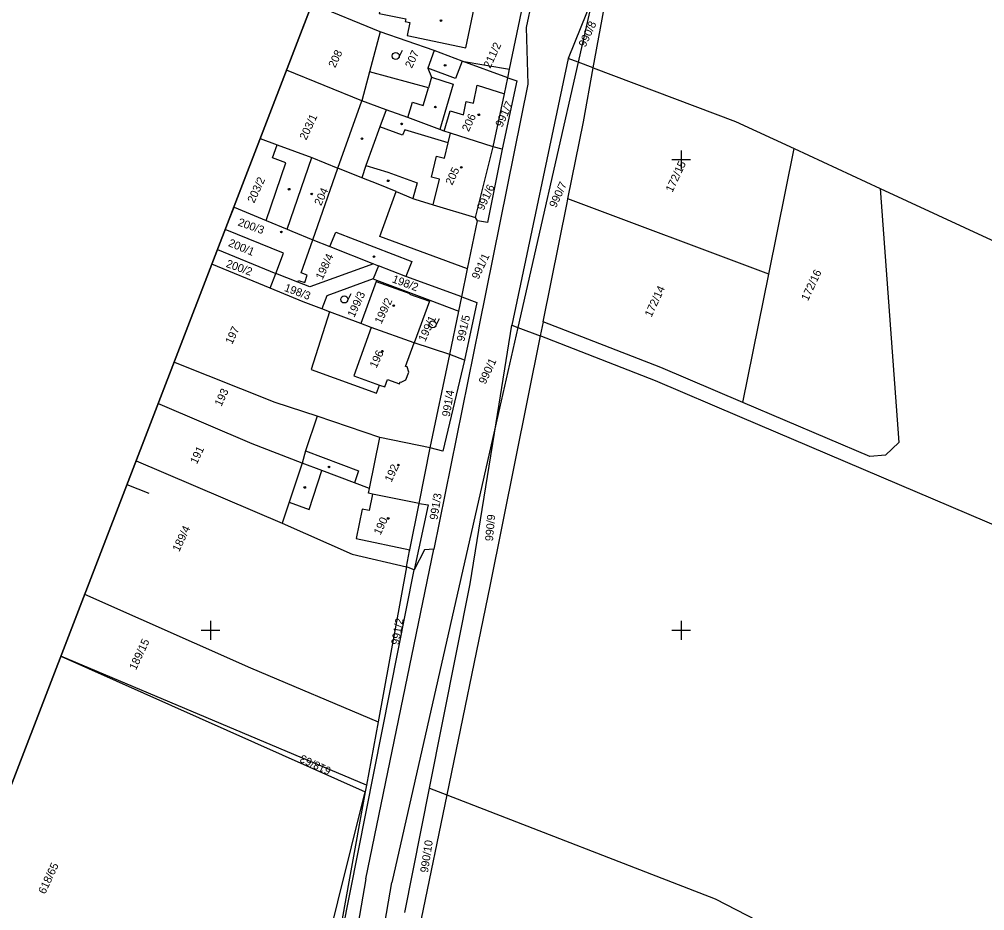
# Model space of a CAD drawing. Extents: x -755344 to -754412, y -1162670 to -1161477.
# Drawn here: x -755140.6 to -754935.5, y -1161959.6 to -1161770.1 of the extents above; entities that cross this region are included whole.
import ezdxf

# ---------------------------------------------------------------- set-up
doc = ezdxf.new("R2010")
doc.units = 0
for name, color, linetype in [('Formát', 7, 'Continuous'), ('Síť', 7, 'Continuous'), ('Vrstva 55', 7, 'Continuous'), ('Vrstva 56', 7, 'Continuous'), ('Vrstva 57', 7, 'Continuous'), ('Vrstva 58', 7, 'Continuous'), ('Vrstva 59', 7, 'Continuous')]:
    doc.layers.add(name, color=color, linetype=linetype)

msp = doc.modelspace()

# ---------------------------------------------------------------- linework, layer by layer
at = {"layer": 'Formát'}
for p, q in [((-755042.37, -1161673.02), (-755344.08, -1162456.97)), ((-755042.37, -1161673.02), (-755344.08, -1162456.97)), ((-755117.8, -1161869.01), (-755113.13, -1161870.81))]:
    msp.add_line(p, q, dxfattribs=at)
msp.add_lwpolyline([(-754488.01, -1161886.37), (-754789.71, -1162670.32), (-755344.08, -1162456.97), (-755042.37, -1161673.02)], close=True, dxfattribs=at)
msp.add_lwpolyline([(-754789.71, -1162670.32), (-754488.01, -1161886.37), (-755042.37, -1161673.02), (-755344.08, -1162456.97)], dxfattribs=at)
at = {"layer": 'Síť'}
for points in [[(-755000, -1161798), (-755000, -1161800), (-755000, -1161802)], [(-754998, -1161800), (-755000, -1161800), (-755002, -1161800)], [(-755100, -1161898), (-755100, -1161900), (-755100, -1161902)], [(-755000, -1161898), (-755000, -1161900), (-755000, -1161902)], [(-755098, -1161900), (-755100, -1161900), (-755102, -1161900)], [(-754998, -1161900), (-755000, -1161900), (-755002, -1161900)]]:
    msp.add_lwpolyline(points, dxfattribs=at)
at = {"layer": 'Vrstva 55'}
for p, q in [((-755036.5, -1161780.73), (-755029.37, -1161746.66)), ((-755018.69, -1161780.44), (-755012.38, -1161745.91)), ((-755018.66, -1161765.05), (-755023.99, -1161778.44)), ((-755063.99, -1161772.75), (-755078.47, -1161766.81)), ((-755063.99, -1161772.75), (-755066.23, -1161781.24)), ((-755052.51, -1161776.75), (-755063.99, -1161772.75)), ((-755046.56, -1161779), (-755052.51, -1161776.75)), ((-755036.87, -1161782.52), (-755046.56, -1161779)), ((-755046.56, -1161779), (-755036.5, -1161780.73)), ((-755023.99, -1161778.44), (-755035.96, -1161835.09)), ((-755067.86, -1161787.41), (-755083.88, -1161780.88)), ((-755066.23, -1161781.24), (-755067.86, -1161787.41)), ((-755036.87, -1161782.52), (-755036.5, -1161780.73)), ((-755072.94, -1161801.75), (-755067.86, -1161787.41)), ((-755038.07, -1161797.72), (-755039.95, -1161797.18)), ((-754981.41, -1161824.3), (-754976.02, -1161797.59)), ((-754976.02, -1161797.59), (-754957.73, -1161806.07)), ((-754981.41, -1161824.3), (-755024.07, -1161808.23)), ((-755095.09, -1161810.02), (-755094.97, -1161810.07)), ((-755094.97, -1161810.07), (-755088.17, -1161812.84)), ((-755045.44, -1161823.16), (-755043.26, -1161812.92)), ((-755098.56, -1161819.02), (-755086.12, -1161824.14)), ((-755087.3, -1161827.26), (-755099.76, -1161822.16)), ((-755064.35, -1161822.48), (-755065.45, -1161825.27)), ((-755065.41, -1161822.06), (-755064.35, -1161822.48)), ((-755087.3, -1161827.26), (-755086.12, -1161824.14)), ((-755081.43, -1161826), (-755086.12, -1161824.14)), ((-755046.61, -1161829.09), (-755045.44, -1161823.16)), ((-754986.91, -1161851.57), (-754981.41, -1161824.3)), ((-755065.45, -1161825.27), (-755064.74, -1161825.54)), ((-755064.74, -1161825.54), (-755053.39, -1161829.8)), ((-755053.39, -1161829.8), (-755047.24, -1161832.11)), ((-755047.24, -1161832.11), (-755046.61, -1161829.09)), ((-755074.72, -1161832.26), (-755076.34, -1161831.64)), ((-755068.04, -1161834.73), (-755074.72, -1161832.26)), ((-755049.18, -1161841.35), (-755047.24, -1161832.11)), ((-755029.36, -1161834.44), (-755029.96, -1161837.42)), ((-755049.18, -1161841.35), (-755056.74, -1161838.86)), ((-755053.32, -1161861.22), (-755049.18, -1161841.35)), ((-755046.01, -1161842.53), (-755049.18, -1161841.35)), ((-755055.68, -1161873.06), (-755053.32, -1161861.22)), ((-755077.79, -1161993.12), (-755056.71, -1161887.12)), ((-755058.39, -1161886.49), (-755064.41, -1161919.47)), ((-755056.71, -1161887.12), (-755058.39, -1161886.49)), ((-755131.83, -1161905.49), (-755067.12, -1161934.32)), ((-755066.86, -1161932.88), (-755131.82, -1161905.45)), ((-755064.41, -1161919.47), (-755066.86, -1161932.88)), ((-755066.86, -1161932.88), (-755067.12, -1161934.32)), ((-755058.72, -1161960), (-755053.45, -1161933.51)), ((-755053.45, -1161933.51), (-755049.81, -1161934.92)), ((-755049.81, -1161934.92), (-755055.25, -1161961.32))]:
    msp.add_line(p, q, dxfattribs=at)
for points in [[(-755013.38, -1161684.18), (-755015.84, -1161699.17), (-755023.66, -1161739.37), (-755030.54, -1161760.43), (-755032.94, -1161771.83), (-755032.59, -1161783.86), (-755042.91, -1161835.1), (-755052.57, -1161882.7), (-755054.53, -1161882.87), (-755056.71, -1161887.12)], [(-755066.7, -1161752.01), (-755068.08, -1161759.03), (-755062.31, -1161760.06), (-755064.15, -1161768.86), (-755058.51, -1161770.01), (-755058.63, -1161770.54), (-755057.66, -1161770.75), (-755058.23, -1161773.52), (-755045.73, -1161776.2), (-755043.71, -1161766.41), (-755042.79, -1161761.96), (-755039.2, -1161744.67), (-755029.37, -1161746.66)], [(-755052.51, -1161776.75), (-755053.85, -1161780.46), (-755053.05, -1161782.42), (-755053.71, -1161784.66), (-755066.23, -1161781.24)], [(-755018.69, -1161780.44), (-755021.88, -1161779.23), (-755023.99, -1161778.44)], [(-755024.07, -1161808.23), (-755020.78, -1161791.91), (-755018.69, -1161780.44)], [(-755018.69, -1161780.44), (-754988.48, -1161791.81), (-754976.02, -1161797.59)], [(-755039.95, -1161797.18), (-755037.58, -1161785.91), (-755036.87, -1161782.52)], [(-755036.87, -1161782.52), (-755034.91, -1161783.19), (-755038.07, -1161797.72)], [(-755039.95, -1161797.18), (-755049.05, -1161794.33), (-755050.33, -1161793.86), (-755051.25, -1161793.52), (-755058.07, -1161791.01), (-755062.7, -1161789.31), (-755067.86, -1161787.41)], [(-755089.48, -1161795.42), (-755085.83, -1161796.77)], [(-755088.17, -1161812.84), (-755084.01, -1161800.63), (-755086.86, -1161799.58), (-755085.83, -1161796.77)], [(-755085.83, -1161796.77), (-755078.48, -1161799.49), (-755072.94, -1161801.75)], [(-755043.26, -1161812.92), (-755043.71, -1161812.24), (-755039.95, -1161797.18)], [(-755038.07, -1161797.72), (-755041.18, -1161813.33), (-755043.26, -1161812.92)], [(-755045.44, -1161823.16), (-755064, -1161816.28), (-755060.56, -1161806.72), (-755064.4, -1161805.16), (-755067.84, -1161803.8), (-755072.94, -1161801.75)], [(-754957.73, -1161806.07), (-754898.34, -1161833.59), (-754912.51, -1161886.53), (-754987.52, -1161854.57), (-755005.46, -1161846.93), (-755029.96, -1161837.42)], [(-754957.73, -1161806.07), (-754953.79, -1161860.09), (-754956.58, -1161862.75), (-754959.95, -1161863.06), (-754986.91, -1161851.57)], [(-755029.36, -1161834.44), (-755024.25, -1161809.12), (-755024.07, -1161808.23)], [(-755086.12, -1161824.14), (-755084.49, -1161819.84), (-755096.9, -1161814.81), (-755094.97, -1161810.07)], [(-755088.17, -1161812.84), (-755083.75, -1161814.68), (-755082.7, -1161815.12), (-755078.25, -1161816.98)], [(-755081.43, -1161826), (-755081.29, -1161825.61), (-755080, -1161826.07), (-755079.47, -1161824.46), (-755080.73, -1161824.02), (-755078.25, -1161816.98)], [(-755078.25, -1161816.98), (-755074.63, -1161818.41), (-755065.41, -1161822.06)], [(-755065.41, -1161822.06), (-755078.92, -1161826.99), (-755081.43, -1161826)], [(-755046.61, -1161829.09), (-755058.54, -1161824.78), (-755064.35, -1161822.48)], [(-755065.45, -1161825.27), (-755075.27, -1161828.85), (-755076.34, -1161831.64)], [(-755064.74, -1161825.54), (-755064.84, -1161825.82), (-755068.04, -1161834.73)], [(-755076.34, -1161831.64), (-755080.31, -1161830.13), (-755087.3, -1161827.26)], [(-755053.39, -1161829.8), (-755053.47, -1161830.02), (-755056.74, -1161838.86)], [(-755046.61, -1161829.09), (-755043.45, -1161830.32), (-755046.01, -1161842.53)], [(-755074.72, -1161832.26), (-755078.65, -1161844.52), (-755064.76, -1161849.59), (-755064.08, -1161847.84), (-755062.95, -1161848.24), (-755062.42, -1161846.64), (-755059.89, -1161847.61), (-755059.74, -1161847.19), (-755059.5, -1161847.27), (-755058.48, -1161846.72), (-755057.9, -1161845.09), (-755058.26, -1161844), (-755058.56, -1161843.89), (-755056.74, -1161838.86)], [(-755056.74, -1161838.86), (-755065.91, -1161835.63), (-755068.04, -1161834.73)], [(-755053.45, -1161933.51), (-755044.81, -1161890.11), (-755039.31, -1161855.89), (-755035.96, -1161835.09)], [(-755035.96, -1161835.09), (-755034.69, -1161835.58), (-755029.96, -1161837.42)], [(-754986.91, -1161851.57), (-755004.33, -1161844.15), (-755029.36, -1161834.44)], [(-755029.96, -1161837.42), (-755040.69, -1161890.6), (-755049.81, -1161934.92)], [(-755077.38, -1161854.48), (-755086.27, -1161851.57), (-755107.78, -1161842.98)], [(-755046.01, -1161842.53), (-755050.67, -1161861.93), (-755053.32, -1161861.22)], [(-755080.57, -1161864.47), (-755091.15, -1161860.37), (-755111.17, -1161851.79)], [(-755077.38, -1161854.48), (-755079.84, -1161861.83), (-755080.57, -1161864.47)], [(-755053.32, -1161861.22), (-755064.04, -1161858.98), (-755077.38, -1161854.48)], [(-755115.84, -1161863.94), (-755084.79, -1161877.24)], [(-755080.57, -1161864.47), (-755083.3, -1161872.73), (-755084.79, -1161877.24)], [(-755055.68, -1161873.06), (-755065.57, -1161871.04), (-755066.47, -1161870.86), (-755066.22, -1161869.81), (-755069.39, -1161868.63), (-755076.39, -1161866.02), (-755080.57, -1161864.47)], [(-755058.39, -1161886.49), (-755057.71, -1161883.06), (-755057.66, -1161882.87), (-755055.68, -1161873.06)], [(-755055.68, -1161873.06), (-755053.78, -1161873.28), (-755056.71, -1161887.12)], [(-755084.79, -1161877.24), (-755069.89, -1161883.79), (-755058.39, -1161886.49)], [(-755126.76, -1161892.31), (-755091.52, -1161907.97), (-755064.41, -1161919.47)], [(-755094.33, -1162027.67), (-755080.69, -1161991.19), (-755079.39, -1161974.89), (-755075.84, -1161969.41), (-755067.12, -1161934.32)], [(-755067.12, -1161934.32), (-755070.48, -1161952.7), (-755077.79, -1161993.12)], [(-755049.81, -1161934.92), (-754992.75, -1161957.04), (-754961.49, -1161973.19), (-754888.73, -1162011.84), (-754815.21, -1162048.8)]]:
    msp.add_lwpolyline(points, dxfattribs=at)
at = {"layer": 'Vrstva 56'}
for p, q in [((-755018.66, -1161765.05), (-755021.88, -1161779.23)), ((-755046.56, -1161779), (-755047.94, -1161782.68)), ((-755021.88, -1161779.23), (-755034.69, -1161835.58)), ((-755047.94, -1161782.68), (-755053.85, -1161780.46)), ((-755053.05, -1161782.42), (-755048.44, -1161783.92)), ((-755054.84, -1161788.43), (-755053.71, -1161784.66)), ((-755048.44, -1161783.92), (-755051.25, -1161793.52)), ((-755044.13, -1161787.9), (-755043.32, -1161784.1)), ((-755043.32, -1161784.1), (-755037.58, -1161785.91)), ((-755058.07, -1161791.01), (-755057.11, -1161787.75)), ((-755057.11, -1161787.75), (-755054.84, -1161788.43)), ((-755046.28, -1161790.43), (-755045.67, -1161787.57)), ((-755045.67, -1161787.57), (-755044.13, -1161787.9)), ((-755062.7, -1161789.31), (-755064.01, -1161792.95)), ((-755050.33, -1161793.86), (-755049.11, -1161789.56)), ((-755049.11, -1161789.56), (-755046.28, -1161790.43)), ((-755064.01, -1161792.95), (-755066.99, -1161801.2)), ((-755059.19, -1161794.76), (-755064.01, -1161792.95)), ((-755058.74, -1161793.58), (-755059.19, -1161794.76)), ((-755049.52, -1161796.33), (-755058.74, -1161793.58)), ((-755049.52, -1161796.33), (-755049.05, -1161794.33)), ((-755050.32, -1161799.64), (-755049.52, -1161796.33)), ((-755083.75, -1161814.68), (-755078.48, -1161799.49)), ((-755053.09, -1161803.64), (-755052.02, -1161799.21)), ((-755052.02, -1161799.21), (-755050.32, -1161799.64)), ((-755078.25, -1161816.98), (-755072.94, -1161801.75)), ((-755066.99, -1161801.2), (-755067.84, -1161803.8)), ((-755066.99, -1161801.2), (-755062.31, -1161802.61)), ((-755062.31, -1161802.61), (-755056.07, -1161804.84)), ((-755051.39, -1161804.05), (-755053.09, -1161803.64)), ((-755052.72, -1161809.52), (-755051.39, -1161804.05)), ((-755056.07, -1161804.84), (-755056.99, -1161808.17)), ((-755060.56, -1161806.72), (-755056.99, -1161808.17)), ((-755056.99, -1161808.17), (-755056.63, -1161808.32)), ((-755056.63, -1161808.32), (-755052.72, -1161809.52)), ((-755052.72, -1161809.52), (-755043.71, -1161812.24)), ((-755074.63, -1161818.41), (-755073.38, -1161815.35)), ((-755073.38, -1161815.35), (-755057.25, -1161821.58)), ((-755057.25, -1161821.58), (-755058.54, -1161824.78)), ((-755064.84, -1161825.82), (-755057.65, -1161828.38)), ((-755057.65, -1161828.38), (-755057.71, -1161828.5)), ((-755057.71, -1161828.5), (-755053.47, -1161830.02)), ((-755065.91, -1161835.63), (-755069.59, -1161845.88)), ((-755034.69, -1161835.58), (-755039.31, -1161855.89)), ((-755069.59, -1161845.88), (-755064.08, -1161847.84)), ((-755039.31, -1161855.89), (-755061.51, -1161953.6)), ((-755066.22, -1161869.81), (-755064.04, -1161858.98)), ((-755079.84, -1161861.83), (-755068.56, -1161866.07)), ((-755079.03, -1161874.3), (-755076.39, -1161866.02)), ((-755068.56, -1161866.07), (-755069.39, -1161868.63)), ((-755065.57, -1161871.04), (-755066.27, -1161874.54)), ((-755083.3, -1161872.73), (-755079.03, -1161874.3)), ((-755067.79, -1161874.23), (-755069.06, -1161880.5)), ((-755066.27, -1161874.54), (-755067.79, -1161874.23)), ((-755069.06, -1161880.5), (-755057.66, -1161882.87)), ((-755067.04, -1161952.84), (-755052.57, -1161882.7)), ((-755067.04, -1161952.84), (-755073.02, -1161988.39)), ((-755067.48, -1161989.17), (-755061.51, -1161953.6))]:
    msp.add_line(p, q, dxfattribs=at)
at = {"layer": 'Vrstva 58'}
for p, q in [((-755059.97, -1161778.21), (-755059.23, -1161776.63)), ((-755070.89, -1161829.96), (-755070.15, -1161828.38)), ((-755052.13, -1161835.26), (-755051.39, -1161833.68))]:
    msp.add_line(p, q, dxfattribs=at)
for centre in [(-755060.65, -1161777.9), (-755071.57, -1161829.65), (-755052.81, -1161834.95)]:
    msp.add_circle(centre, 0.75, dxfattribs=at)
at = {"layer": 'Vrstva 59'}
for centre in [(-755051.02, -1161770.37), (-755050.16, -1161779.87), (-755052.24, -1161788.75), (-755043.01, -1161790.4), (-755059.4, -1161792.33), (-755067.84, -1161795.48), (-755046.73, -1161801.57), (-755062.26, -1161804.43), (-755083.3, -1161806.22), (-755078.51, -1161807.22), (-755084.96, -1161815.31), (-755065.27, -1161820.54), (-755061.09, -1161830.96), (-755063.51, -1161840.65), (-755074.85, -1161865.26), (-755060.12, -1161864.87), (-755079.98, -1161869.62), (-755062.25, -1161876.21)]:
    msp.add_circle(centre, 0.175, dxfattribs=at)

# ---------------------------------------------------------------- texts
at = {"layer": 'Vrstva 57'}
for s, rotation, p in [('990/8', 65, (-755020.36, -1161776.16)), ('211/2', 65, (-755040.58, -1161780.65)), ('208', 65, (-755073.53, -1161780.54)), ('207', 65, (-755057.24, -1161780.64)), ('991/7', 65, (-755038.05, -1161793.18)), ('203/1', 65, (-755079.67, -1161795.9)), ('206', 65, (-755045.15, -1161794.1)), ('172/15', 65, (-755001.87, -1161807.01)), ('205', 65, (-755048.66, -1161805.49)), ('203/2', 65, (-755090.74, -1161809.29)), ('204', 65, (-755076.53, -1161809.86)), ('991/6', 65, (-755041.99, -1161810.86)), ('990/7', 65, (-755026.62, -1161810.3)), ('200/3', 340.5336, (-755094.33, -1161813.9)), ('200/1', 337.6705, (-755096.37, -1161818.26)), ('198/4', 65, (-755076.22, -1161825.58)), ('991/1', 65, (-755043.08, -1161825.51)), ('200/2', 340, (-755096.85, -1161822.7)), ('198/2', 339.5705, (-755061.56, -1161825.97)), ('172/16', 65, (-754973.07, -1161830.1)), ('198/3', 339.6039, (-755084.47, -1161827.81)), ('172/14', 65, (-755006.33, -1161833.55)), ('199/3', 65, (-755069.48, -1161833.6)), ('199/2', 65, (-755063.71, -1161834.99)), ('991/5', 77.0202, (-755046.1, -1161838.73)), ('199/1', 65, (-755054.41, -1161838.77)), ('197', 65, (-755095.42, -1161839.32)), ('196', 65, (-755064.77, -1161844.39)), ('990/1', 65, (-755041.6, -1161847.81)), ('193', 65, (-755097.71, -1161852.52)), ('991/4', 80.3171, (-755049.19, -1161854.68)), ('191', 65, (-755102.91, -1161864.78)), ('192', 65, (-755061.57, -1161868.62)), ('991/3', 80.3378, (-755051.82, -1161876.6)), ('190', 65, (-755063.9, -1161879.86)), ('990/9', 84.9969, (-755040, -1161881.1)), ('189/4', 65, (-755106.66, -1161883.41)), ('991/2', 79.8632, (-755059.99, -1161903.18)), ('189/15', 65, (-755115.86, -1161908.58)), ('618/63', 155, (-755074.21, -1161929.29)), ('990/10', 81.3254, (-755053.81, -1161951.59)), ('618/65', 65, (-755135.16, -1161956.19))]:
    msp.add_text(s, height=1.7, rotation=rotation, dxfattribs=at).set_placement(p)

doc.saveas('drawing.dxf')
